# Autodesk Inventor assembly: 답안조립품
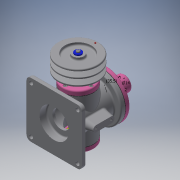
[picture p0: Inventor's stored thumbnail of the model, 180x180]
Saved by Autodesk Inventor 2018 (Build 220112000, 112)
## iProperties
Created: 2020-02
Part Number: 답안조립품
Document SubType Name: Assembly
Designer: Administrator
Author: Administrator
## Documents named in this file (21)
- C:\Users\Administrator\Desktop\600206V1022\답안조립품.iam
- C:\Users\Administrator\Desktop\600206V1022\본체.ipt
- C:\Users\Administrator\Desktop\600206V1022\개스킷 B.ipt
- C:\Users\Administrator\Desktop\600206V1022\개스킷 A.ipt
- C:\Users\Administrator\Desktop\600206V1022\덮개.ipt
- C:\Users\Administrator\Desktop\600206V1022\앞커버.ipt
- C:\Users\Administrator\Desktop\600206V1022\뒤커버.ipt
- C:\Users\Administrator\Desktop\600206V1022\편심축.ipt
- C:\Users\Administrator\Desktop\600206V1022\베어링 17 x 40 x 12.ipt
- C:\Users\Administrator\Desktop\600206V1022\링크.ipt
- C:\Users\Administrator\Desktop\600206V1022\슬라이더.ipt
- C:\Users\Administrator\Desktop\600206V1022\클레비스 핀 6 x 22.ipt
- 클레비스 핀 6 x 22.ipt
- C:\Users\Administrator\Desktop\600206V1022\E-링.ipt
- C:\Users\Administrator\Desktop\600206V1022\오일 실 17 30 8.ipt
- C:\Users\Administrator\Desktop\600206V1022\키 4 x 4 x 25.ipt
- C:\Users\Administrator\Desktop\600206V1022\V-벨트풀리.ipt
- C:\Users\Administrator\Desktop\600206V1022\와셔 4x16.ipt
- C:\Users\Administrator\Desktop\600206V1022\볼트 M4 x 10.ipt
- C:\Users\Administrator\Desktop\600206V1022\육각 소켓 머리 볼트 M4 x 10.ipt
- C:\Users\Administrator\Desktop\600206V1022\가변스프링.ipt
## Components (6 placed, 5 different names)
1. 개스킷 B:1
2. 개스킷 A:1
3. 개스킷 A:2
4. E-링:1
5. V-벨트풀리:1 — 플러쉬:1
6. 가변스프링:1
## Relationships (1: Flush 1)
- 플러쉬:1 [Flush]: V-벨트풀리:1
